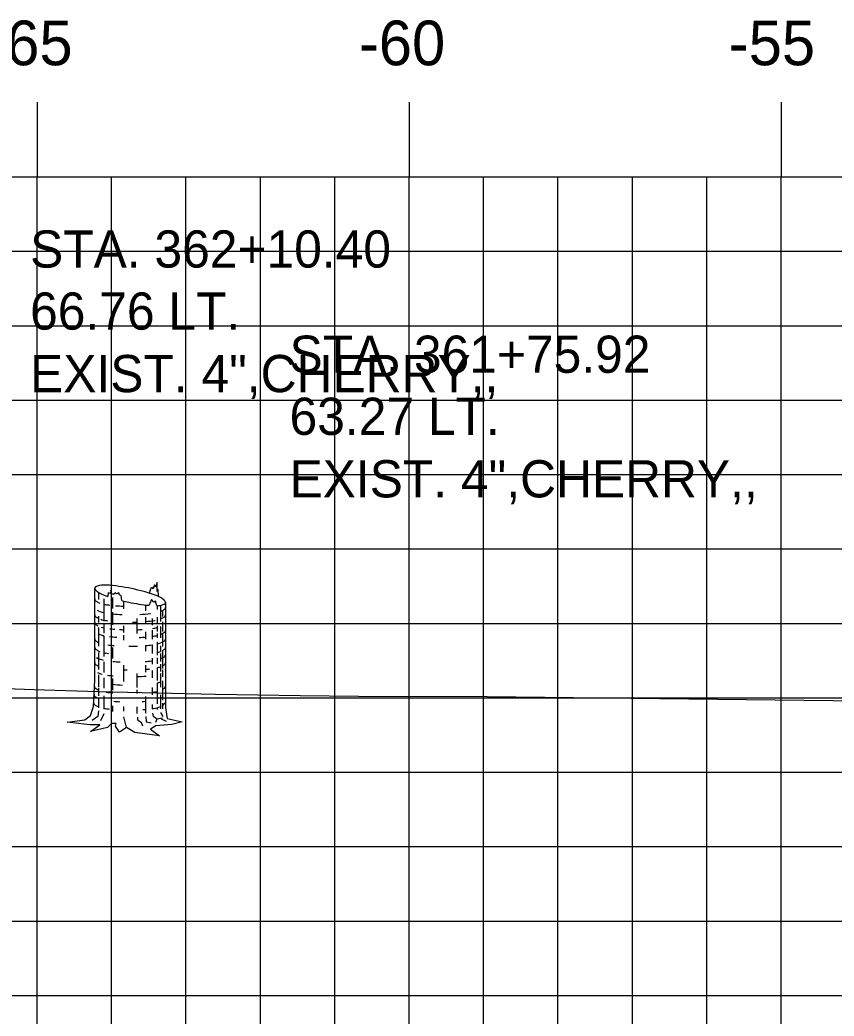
# Model space of a CAD drawing. Extents: x 1146746 to 1146916, y 608981 to 609091.
# Drawn here: x 1146764.2 to 1146775.14, y 609029.06 to 609042.44 of the extents above; entities that cross this region are included whole.
import ezdxf

# ---------------------------------------------------------------- set-up
doc = ezdxf.new("R2010")
doc.units = 0
for name, color, linetype in [('D_Text_Monospaced', 7, 'Continuous'), ('H_V ANNOTATION', 7, 'Continuous'), ('MAJOR', 7, 'Continuous'), ('MINOR', 7, 'Continuous'), ('S_Roadway_Centerline', 7, 'Continuous'), ('S_Trees_Decid_NonPay', 7, 'Continuous')]:
    doc.layers.add(name, color=color, linetype=linetype)

msp = doc.modelspace()

# ---------------------------------------------------------------- linework, layer by layer
at = {"layer": 'MAJOR'}
for p, q in [((1146764.428, 609041.337), (1146764.428, 609040.335)), ((1146769.428, 609041.337), (1146769.428, 609040.335)), ((1146774.428, 609041.337), (1146774.428, 609040.335)), ((1146759.428, 609040.335), (1146899.428, 609040.335)), ((1146759.428, 609040.335), (1146899.428, 609040.335)), ((1146764.428, 609020.335), (1146764.428, 609040.335)), ((1146769.428, 609020.335), (1146769.428, 609040.335)), ((1146774.428, 609020.335), (1146774.428, 609040.335)), ((1146759.428, 609035.335), (1146899.428, 609035.335)), ((1146759.428, 609030.335), (1146899.428, 609030.335))]:
    msp.add_line(p, q, dxfattribs=at)
at = {"layer": 'MINOR'}
for p, q in [((1146765.428, 609020.335), (1146765.428, 609040.335)), ((1146766.428, 609020.335), (1146766.428, 609040.335)), ((1146767.428, 609020.335), (1146767.428, 609040.335)), ((1146768.428, 609020.335), (1146768.428, 609040.335)), ((1146770.428, 609020.335), (1146770.428, 609040.335)), ((1146771.428, 609020.335), (1146771.428, 609040.335)), ((1146772.428, 609020.335), (1146772.428, 609040.335)), ((1146773.428, 609020.335), (1146773.428, 609040.335)), ((1146759.428, 609039.335), (1146899.428, 609039.335)), ((1146759.428, 609038.335), (1146899.428, 609038.335)), ((1146759.428, 609037.335), (1146899.428, 609037.335)), ((1146759.428, 609036.335), (1146899.428, 609036.335)), ((1146759.428, 609034.335), (1146899.428, 609034.335)), ((1146759.428, 609033.335), (1146899.428, 609033.335)), ((1146759.428, 609032.335), (1146899.428, 609032.335)), ((1146759.428, 609031.335), (1146899.428, 609031.335)), ((1146759.428, 609029.335), (1146899.428, 609029.335))]:
    msp.add_line(p, q, dxfattribs=at)
at = {"layer": 'S_Roadway_Centerline'}
msp.add_lwpolyline([(1146759.428, 609033.556), (1146762.881, 609033.501), (1146764.381, 609033.447), (1146765.249, 609033.421), (1146766.824, 609033.384), (1146767.963, 609033.367), (1146768.745, 609033.359), (1146770.475, 609033.354), (1146778.994, 609033.253), (1146779.894, 609033.259), (1146781.955, 609033.29), (1146784.763, 609033.357), (1146788.214, 609033.405), (1146790.04, 609033.481), (1146792.515, 609033.614), (1146794.858, 609033.519)], dxfattribs=at)
at = {"layer": 'S_Trees_Decid_NonPay'}
for p, q in [((1146765.254, 609034.752), (1146765.254, 609034.657)), ((1146765.322, 609034.665), (1146765.322, 609034.364)), ((1146765.441, 609034.682), (1146765.441, 609034.534)), ((1146765.588, 609034.636), (1146765.588, 609034.529)), ((1146765.885, 609034.584), (1146765.885, 609034.505)), ((1146766.043, 609034.573), (1146766.043, 609034.521)), ((1146766.085, 609034.578), (1146766.085, 609034.36)), ((1146766.112, 609034.508), (1146766.112, 609034.426)), ((1146765.254, 609034.431), (1146765.254, 609034.348)), ((1146765.441, 609034.486), (1146765.441, 609034.317)), ((1146765.768, 609034.4), (1146765.768, 609034.2)), ((1146765.885, 609034.418), (1146765.885, 609034.334)), ((1146765.972, 609034.4), (1146765.972, 609034.313)), ((1146766.043, 609034.418), (1146766.043, 609034.336)), ((1146765.254, 609034.278), (1146765.254, 609034.027)), ((1146765.322, 609034.336), (1146765.322, 609034.204)), ((1146765.588, 609034.301), (1146765.588, 609034.214)), ((1146765.972, 609034.243), (1146765.972, 609034.122)), ((1146766.043, 609034.301), (1146766.043, 609034.227)), ((1146766.085, 609034.292), (1146766.085, 609034.14)), ((1146766.112, 609034.357), (1146766.112, 609034.227)), ((1146765.322, 609034.17), (1146765.322, 609033.889)), ((1146765.588, 609034.179), (1146765.588, 609034.109)), ((1146765.885, 609034.223), (1146765.885, 609034.122)), ((1146766.043, 609034.2), (1146766.043, 609034.14)), ((1146766.112, 609034.204), (1146766.112, 609034.023)), ((1146765.441, 609034.011), (1146765.441, 609033.862)), ((1146765.885, 609034.037), (1146765.885, 609033.961)), ((1146765.972, 609034.046), (1146765.972, 609033.932)), ((1146766.043, 609034.087), (1146766.043, 609033.906)), ((1146766.085, 609034.035), (1146766.085, 609033.957)), ((1146766.112, 609033.975), (1146766.112, 609033.729)), ((1146765.254, 609033.944), (1146765.254, 609033.714)), ((1146765.972, 609033.87), (1146765.972, 609033.788)), ((1146766.043, 609033.874), (1146766.043, 609033.792)), ((1146766.085, 609033.93), (1146766.085, 609033.823)), ((1146765.322, 609033.819), (1146765.322, 609033.675)), ((1146765.588, 609033.776), (1146765.588, 609033.553)), ((1146765.885, 609033.776), (1146765.885, 609033.679)), ((1146766.043, 609033.738), (1146766.043, 609033.568)), ((1146766.085, 609033.788), (1146766.085, 609033.687)), ((1146766.112, 609033.71), (1146766.112, 609033.615)), ((1146765.254, 609033.644), (1146765.254, 609033.483)), ((1146765.322, 609033.605), (1146765.322, 609033.463)), ((1146765.441, 609033.593), (1146765.441, 609033.44)), ((1146765.768, 609033.662), (1146765.768, 609033.475)), ((1146765.972, 609033.702), (1146765.972, 609033.605)), ((1146766.085, 609033.662), (1146766.085, 609033.479)), ((1146765.254, 609033.467), (1146765.254, 609033.362)), ((1146765.768, 609033.444), (1146765.768, 609033.391)), ((1146765.972, 609033.475), (1146765.972, 609033.376)), ((1146766.043, 609033.534), (1146766.043, 609033.255)), ((1146766.114, 609033.562), (1146766.113, 609033.302)), ((1146765.254, 609033.325), (1146765.254, 609033.201)), ((1146765.322, 609033.362), (1146765.322, 609033.181)), ((1146765.885, 609033.354), (1146765.885, 609033.13)), ((1146766.085, 609033.376), (1146766.085, 609033.185)), ((1146765.441, 609033.228), (1146765.441, 609033.15)), ((1146765.588, 609033.22), (1146765.588, 609033.154)), ((1146765.768, 609033.215), (1146765.768, 609033.125)), ((1146765.972, 609033.247), (1146765.972, 609033.189)), ((1146766.043, 609033.202), (1146766.043, 609033.177)), ((1146766.112, 609033.263), (1146766.112, 609033.189)), ((1146765.322, 609033.121), (1146765.28, 609033.025)), ((1146765.628, 609032.934), (1146765.593, 609033.08)), ((1146766.084, 609033.137), (1146766.118, 609033.086)), ((1146766.166, 609033.016), (1146766.098, 609033.047))]:
    msp.add_line(p, q, dxfattribs=at)
for points in [[(1146766.154, 609034.616), (1146766.154, 609033.204), (1146766.176, 609033.055), (1146766.379, 609033.012), (1146766.24, 609032.977), (1146766.021, 609032.958), (1146765.952, 609032.915), (1146766.073, 609032.826), (1146765.742, 609032.87), (1146765.628, 609032.934), (1146765.536, 609032.874), (1146765.48, 609032.952), (1146765.488, 609032.989), (1146765.427, 609032.991), (1146765.375, 609032.934), (1146765.143, 609032.882), (1146765.27, 609032.971), (1146765.138, 609032.973), (1146764.83, 609033.01), (1146765.068, 609033.041), (1146765.147, 609033.099), (1146765.185, 609033.22), (1146765.202, 609033.574), (1146765.202, 609034.807)], [(1146765.566, 609034.641), (1146765.558, 609034.708), (1146765.534, 609034.713), (1146765.525, 609034.748), (1146765.494, 609034.733), (1146765.48, 609034.748), (1146765.456, 609034.725), (1146765.433, 609034.733), (1146765.42, 609034.782), (1146765.412, 609034.739), (1146765.381, 609034.748), (1146765.378, 609034.696)], [(1146766.059, 609034.696), (1146766.055, 609034.791), (1146766.04, 609034.764), (1146766.04, 609034.885), (1146766.019, 609034.822), (1146766.005, 609034.855), (1146765.988, 609034.799), (1146765.972, 609034.816), (1146765.954, 609034.807), (1146765.935, 609034.74)], [(1146766.036, 609034.572), (1146766.019, 609034.634), (1146765.997, 609034.622), (1146765.966, 609034.657), (1146765.933, 609034.579)], [(1146765.251, 609033.158), (1146765.243, 609033.082), (1146765.165, 609033.032)], [(1146765.776, 609033.076), (1146765.776, 609033.039), (1146765.828, 609033.008), (1146765.845, 609032.958)], [(1146765.888, 609033.082), (1146765.894, 609033.012), (1146765.958, 609033)], [(1146766.036, 609033.047), (1146765.992, 609033.082), (1146765.984, 609033.13)], [(1146766.114, 609033.063), (1146766.036, 609033.047), (1146766.019, 609033.004)]]:
    msp.add_lwpolyline(points, dxfattribs=at)
for centre, radius, start, end in [((1146765.22, 609034.807), 0.0179, 152.1168, 168.1723), ((1146765.22, 609034.807), 0.0179, 168.1723, 184.2278), ((1146765.226, 609034.808), 0.0237, 184.2278, 198.1723), ((1146765.236, 609034.811), 0.0336, 198.1723, 216.9486), ((1146765.226, 609034.805), 0.0237, 138.1723, 152.1168), ((1146765.233, 609034.798), 0.0336, 119.396, 138.1723), ((1146765.284, 609034.847), 0.0935, 216.9486, 228.1723), ((1146765.262, 609034.746), 0.0935, 108.1723, 119.396), ((1146765.436, 609035.017), 0.322, 228.1723, 250.2902), ((1146765.334, 609034.529), 0.322, 86.0543, 108.1723), ((1146765.183, 609032.349), 2.507, 78.1723, 86.0543), ((1146765.183, 609032.349), 2.507, 70.2902, 78.1723), ((1146765.221, 609034.66), 0.0191, 163.9485, 180), ((1146765.221, 609034.66), 0.0191, 180, 196.0515), ((1146765.227, 609034.662), 0.0252, 196.0515, 210), ((1146765.236, 609034.667), 0.0356, 210, 228.7494), ((1146765.277, 609034.714), 0.0984, 228.7494, 240), ((1146766.173, 609037.074), 2.507, 250.2902, 251.5281), ((1146766.173, 609037.074), 2.507, 255.9987, 258.1723), ((1146765.92, 609034.406), 0.322, 48.1723, 70.2902), ((1146766.072, 609034.576), 0.0935, 36.9486, 48.1723), ((1146765.391, 609034.911), 0.326, 240, 248.3243), ((1146765.391, 609034.798), 0.326, 240.9099, 257.8036), ((1146765.391, 609034.911), 0.326, 257.8036, 261.8968), ((1146765.677, 609036.921), 2.356, 261.8968, 263.2799), ((1146765.677, 609036.921), 2.356, 265.24, 267.8386), ((1146766.173, 609037.074), 2.507, 258.1723, 264.5013), ((1146766.022, 609034.894), 0.322, 272.4479, 288.1723), ((1146765.963, 609034.798), 0.326, 291.9506, 300), ((1146766.094, 609034.677), 0.0935, 288.1723, 299.396), ((1146766.077, 609034.601), 0.0984, 300, 311.2506), ((1146766.123, 609034.625), 0.0336, 299.396, 318.1723), ((1146766.119, 609034.554), 0.0356, 311.2506, 330), ((1146766.12, 609034.612), 0.0336, 18.1723, 36.9486), ((1146766.13, 609034.618), 0.0237, 318.1723, 332.1168), ((1146766.128, 609034.548), 0.0252, 330, 343.9485), ((1146766.135, 609034.616), 0.0179, 332.1168, 348.1723), ((1146766.13, 609034.615), 0.0237, 4.2278, 18.1723), ((1146766.134, 609034.547), 0.0191, 343.9485, 360), ((1146766.135, 609034.616), 0.0179, 348.1723, 4.2278), ((1146766.134, 609034.547), 0.0191, 360, 6.1128), ((1146765.221, 609034.446), 0.0191, 163.9485, 180), ((1146765.221, 609034.446), 0.0191, 180, 196.0515), ((1146765.227, 609034.448), 0.0252, 196.0515, 210), ((1146765.236, 609034.453), 0.0356, 210, 228.7494), ((1146765.277, 609034.5), 0.0984, 228.7494, 240), ((1146765.391, 609034.697), 0.326, 240, 243.5719), ((1146765.391, 609034.697), 0.326, 250.4167, 261.8968), ((1146765.677, 609036.707), 2.356, 261.8968, 262.5519), ((1146765.677, 609036.808), 2.356, 264.242, 267.3673), ((1146765.677, 609036.808), 2.356, 273.1481, 276.7734), ((1146765.677, 609036.707), 2.356, 275.0647, 278.1032), ((1146765.963, 609034.697), 0.326, 278.1032, 279.0854), ((1146765.963, 609034.697), 0.326, 291.9506, 300), ((1146766.077, 609034.5), 0.0984, 300, 311.2506), ((1146766.119, 609034.453), 0.0356, 311.2506, 330), ((1146766.128, 609034.448), 0.0252, 330, 343.9485), ((1146766.134, 609034.446), 0.0191, 343.9485, 360), ((1146766.134, 609034.446), 0.0191, 360, 6.1128), ((1146765.221, 609034.343), 0.0191, 163.9485, 180), ((1146765.221, 609034.343), 0.0191, 180, 196.0515), ((1146765.227, 609034.345), 0.0252, 196.0515, 210), ((1146765.236, 609034.35), 0.0356, 210, 228.7494), ((1146765.277, 609034.397), 0.0984, 228.7494, 240), ((1146765.391, 609034.594), 0.326, 240, 243.243), ((1146765.391, 609034.594), 0.326, 251.6831, 257.8036), ((1146765.677, 609036.604), 2.356, 263.3413, 264.9946), ((1146765.677, 609036.604), 2.356, 266.5036, 267.8386), ((1146765.677, 609036.707), 2.356, 270.8119, 272.1981), ((1146765.677, 609036.604), 2.356, 272.1981, 273.9741), ((1146765.677, 609036.604), 2.356, 277.3838, 278.1032), ((1146765.963, 609034.594), 0.326, 278.1032, 284.0382), ((1146766.134, 609034.343), 0.0191, 343.9485, 360), ((1146766.134, 609034.343), 0.0191, 360, 6.1128), ((1146766.134, 609034.238), 0.0191, 360, 6.1128), ((1146765.221, 609034.123), 0.0191, 163.9485, 180), ((1146765.221, 609034.123), 0.0191, 180, 196.0515), ((1146765.227, 609034.125), 0.0252, 196.0515, 210), ((1146765.236, 609034.13), 0.0356, 210, 228.7494), ((1146765.391, 609034.489), 0.326, 245.1545, 257.8036), ((1146765.677, 609036.499), 2.356, 263.2682, 265.6362), ((1146765.677, 609036.499), 2.356, 273.0067, 275.0647), ((1146765.677, 609036.499), 2.356, 277.1868, 278.1032), ((1146765.963, 609034.489), 0.326, 278.1032, 284.0382), ((1146765.963, 609034.489), 0.326, 291.9506, 300), ((1146766.077, 609034.292), 0.0984, 300, 311.2506), ((1146766.119, 609034.245), 0.0356, 311.2506, 330), ((1146766.119, 609034.13), 0.0356, 311.2506, 330), ((1146766.128, 609034.24), 0.0252, 330, 343.9485), ((1146766.128, 609034.125), 0.0252, 330, 343.9485), ((1146766.134, 609034.238), 0.0191, 343.9485, 360), ((1146766.134, 609034.123), 0.0191, 343.9485, 360), ((1146766.134, 609034.123), 0.0191, 360, 6.1128), ((1146765.222, 609034.008), 0.0191, 163.9485, 180), ((1146765.222, 609034.008), 0.0191, 180, 196.0515), ((1146765.228, 609034.01), 0.0252, 196.0515, 210), ((1146765.237, 609034.015), 0.0356, 210, 228.7494), ((1146765.277, 609034.177), 0.0984, 228.7494, 240), ((1146765.278, 609034.063), 0.0984, 228.7494, 240), ((1146765.391, 609034.374), 0.326, 240, 245.1545), ((1146765.392, 609034.26), 0.326, 240, 247.8656), ((1146765.677, 609036.384), 2.356, 262.6588, 264.7911), ((1146765.677, 609036.384), 2.356, 269.5578, 270), ((1146765.677, 609036.384), 2.356, 270, 272.414), ((1146765.677, 609036.384), 2.356, 275.0647, 277.1868), ((1146765.963, 609034.374), 0.326, 284.0382, 300), ((1146765.964, 609034.26), 0.326, 297.0058, 300), ((1146766.077, 609034.177), 0.0984, 300, 311.2506), ((1146766.078, 609034.063), 0.0984, 300, 311.2506), ((1146766.119, 609034.015), 0.0356, 311.2506, 330), ((1146766.128, 609034.01), 0.0252, 330, 343.9485), ((1146766.134, 609034.008), 0.0191, 0, 6.1128), ((1146766.134, 609034.008), 0.0191, 343.9485, 360), ((1146765.218, 609033.908), 0.0191, 163.9485, 180), ((1146765.389, 609034.159), 0.326, 240, 256.9079), ((1146765.392, 609034.26), 0.326, 257.6699, 261.8968), ((1146765.678, 609036.27), 2.356, 261.8968, 262.8615), ((1146765.964, 609034.26), 0.326, 283.9036, 291.8098), ((1146765.961, 609034.159), 0.326, 292.4049, 300), ((1146766.075, 609033.962), 0.0984, 300, 311.2506), ((1146766.116, 609033.915), 0.0356, 311.2506, 330), ((1146766.125, 609033.91), 0.0252, 330, 343.9485), ((1146766.131, 609033.908), 0.0191, 0, 6.1128), ((1146766.131, 609033.908), 0.0191, 343.9485, 360), ((1146765.221, 609033.803), 0.0191, 163.9485, 180), ((1146765.221, 609033.803), 0.0191, 180, 196.0515), ((1146765.227, 609033.805), 0.0252, 196.0515, 210), ((1146765.236, 609033.81), 0.0356, 210, 228.7494), ((1146765.277, 609033.858), 0.0984, 228.7494, 240), ((1146765.391, 609034.055), 0.326, 240, 245.1545), ((1146765.675, 609036.169), 2.356, 264.3443, 266.8529), ((1146765.677, 609036.065), 2.356, 267.8386, 269.0054), ((1146765.675, 609036.169), 2.356, 274.9734, 277.2455), ((1146765.677, 609036.065), 2.356, 275.0647, 276.428), ((1146765.963, 609034.055), 0.326, 284.0382, 291.9506), ((1146765.963, 609034.055), 0.326, 297.1525, 300), ((1146766.077, 609033.858), 0.0984, 300, 311.2506), ((1146766.119, 609033.81), 0.0356, 311.2506, 330), ((1146766.128, 609033.805), 0.0252, 330, 343.9485), ((1146766.134, 609033.803), 0.0191, 343.9485, 360), ((1146766.134, 609033.803), 0.0191, 360, 6.1128), ((1146766.134, 609033.713), 0.0191, 360, 6.1128), ((1146765.391, 609033.964), 0.326, 241.939, 253.9183), ((1146765.677, 609035.974), 2.356, 262.5843, 264.4865), ((1146765.677, 609035.974), 2.356, 272.1981, 275.2726), ((1146765.217, 609033.484), 0.0191, 163.9485, 180), ((1146765.217, 609033.484), 0.0191, 180, 196.0515), ((1146765.223, 609033.486), 0.0252, 196.0515, 210), ((1146765.232, 609033.491), 0.0356, 210, 228.7494), ((1146765.273, 609033.539), 0.0984, 228.7494, 240), ((1146765.387, 609033.736), 0.326, 240, 245.9375), ((1146765.677, 609035.861), 2.356, 264.242, 267.469), ((1146765.963, 609033.851), 0.326, 284.0382, 291.9506), ((1146766.073, 609033.539), 0.0984, 300, 311.2506), ((1146766.115, 609033.491), 0.0356, 311.2506, 330), ((1146766.124, 609033.486), 0.0252, 330, 343.9485), ((1146766.13, 609033.484), 0.0191, 343.9485, 360), ((1146766.13, 609033.484), 0.0191, 360, 6.1128), ((1146765.212, 609033.374), 0.0191, 163.9485, 180), ((1146765.212, 609033.374), 0.0191, 180, 196.0515), ((1146765.218, 609033.375), 0.0252, 196.0515, 210), ((1146765.227, 609033.381), 0.0356, 210, 228.7494), ((1146765.268, 609033.428), 0.0984, 228.7494, 240), ((1146765.382, 609033.625), 0.326, 240, 241.9097), ((1146765.673, 609035.746), 2.356, 262.2226, 264.4852), ((1146765.673, 609035.746), 2.356, 277.2863, 278.1032), ((1146765.959, 609033.736), 0.326, 278.1032, 284.7741), ((1146765.954, 609033.625), 0.326, 293.6544, 300), ((1146765.206, 609033.264), 0.0191, 163.9485, 180), ((1146765.206, 609033.264), 0.0191, 180, 196.0515), ((1146765.212, 609033.265), 0.0252, 196.0515, 210), ((1146765.221, 609033.27), 0.0356, 210, 228.7494), ((1146765.263, 609033.318), 0.0984, 228.7494, 240), ((1146765.377, 609033.515), 0.326, 240, 247.9161), ((1146765.377, 609033.515), 0.326, 260.3834, 261.8968), ((1146765.663, 609035.525), 2.356, 261.8968, 263.5333), ((1146765.668, 609035.635), 2.356, 264.9089, 266.8158), ((1146765.668, 609035.635), 2.356, 274.1864, 275.2829), ((1146765.663, 609035.525), 2.356, 274.5551, 275.4167), ((1146765.663, 609035.525), 2.356, 277.5403, 278.1032), ((1146765.949, 609033.515), 0.326, 278.1032, 294.7094), ((1146766.063, 609033.318), 0.0984, 300, 311.2506), ((1146766.104, 609033.27), 0.0356, 311.2506, 330), ((1146766.113, 609033.265), 0.0252, 330, 343.9485), ((1146766.119, 609033.264), 0.0191, 0, 6.1128), ((1146766.119, 609033.264), 0.0191, 343.9485, 360)]:
    msp.add_arc(centre, radius, start, end, dxfattribs=at)

# ---------------------------------------------------------------- texts
at = {"layer": 'D_Text_Monospaced'}
for s, height, p in [('STA. 362+10.40', 0.49998, (1146764.333, 609039.116)), ('66.76 LT.', 0.5, (1146764.333, 609038.282)), ('STA. 361+75.92', 0.49998, (1146767.82, 609037.702)), ('EXIST. 4",CHERRY,,', 0.49998, (1146764.333, 609037.442)), ('63.27 LT.', 0.5, (1146767.82, 609036.868)), ('EXIST. 4",CHERRY,,', 0.49998, (1146767.82, 609036.028))]:
    msp.add_text(s, height=height, dxfattribs=at).set_placement(p)
at = {"layer": 'H_V ANNOTATION'}
for s, p in [('-65', (1146763.745, 609041.835)), ('-60', (1146768.753, 609041.835)), ('-55', (1146773.724, 609041.835))]:
    msp.add_text(s, height=0.6, dxfattribs=at).set_placement(p)

doc.saveas('drawing.dxf')
